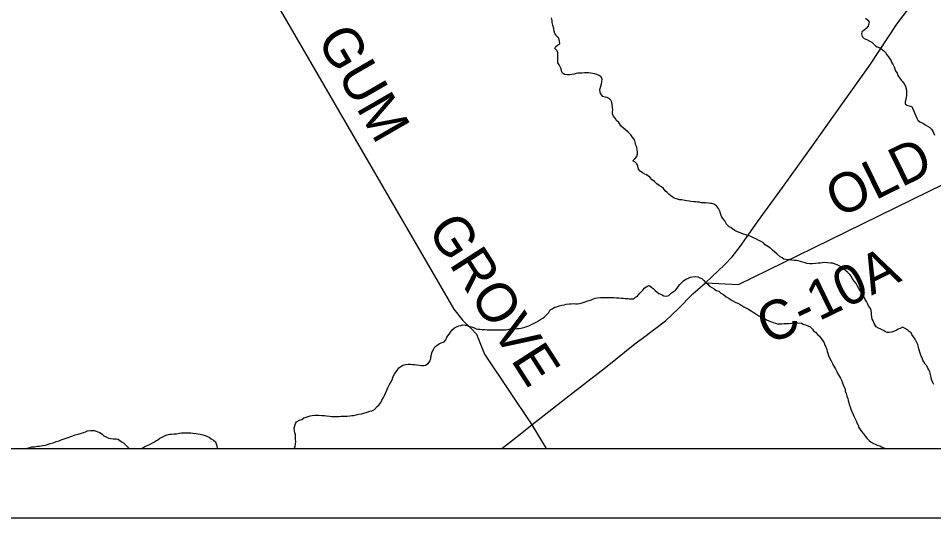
# Model space of a CAD drawing. Extents: x 0.4 to 34.4, y -2.1 to 19.9.
# Drawn here: x 7.097 to 8.419, y 11.936 to 12.657 of the extents above; entities that cross this region are included whole.
import ezdxf

# ---------------------------------------------------------------- set-up
doc = ezdxf.new("R2010")
doc.units = 0
for name, color, linetype in [('GM_X_County', 7, 'Continuous'), ('GM_X_County_Road', 7, 'Continuous'), ('GM_X_County_Road_Text', 7, 'Continuous'), ('GM_X_Minor_River', 7, 'Continuous'), ('GM_X_Township', 7, 'Continuous'), ('GM_X_Township_Road', 7, 'Continuous'), ('GM_X_Township_Road_Text', 7, 'Continuous'), ('GM_X_US_Route', 7, 'Continuous'), ('SH_Data', 7, 'Continuous')]:
    doc.layers.add(name, color=color, linetype=linetype)

msp = doc.modelspace()

# ---------------------------------------------------------------- linework, layer by layer
at = {"layer": 'GM_X_County'}
msp.add_lwpolyline([(9.8001, 15.3423), (9.8001, 18.8357), (3.0001, 18.8357), (3.0001, 12.0357), (9.5074, 12.0357)], dxfattribs=at)
at = {"layer": 'GM_X_County_Road'}
msp.add_lwpolyline([(8.0891, 12.2752), (8.137, 12.2725), (8.245, 12.3255), (8.4821, 12.4414), (8.5989, 12.4995), (8.628, 12.5138), (8.6707, 12.5221), (8.7165, 12.5201), (8.7516, 12.5061), (8.8108, 12.4713), (8.8447, 12.457), (8.8853, 12.4579)], dxfattribs=at)
at = {"layer": 'GM_X_Minor_River'}
for points in [[(8.0158, 12.4213), (8.0121, 12.4236), (8.0087, 12.4275), (8.0042, 12.431), (8.0016, 12.4322), (7.9982, 12.4341), (7.9948, 12.4361), (7.9926, 12.4392), (7.9915, 12.4434), (7.9901, 12.4468), (7.9879, 12.4495), (7.9845, 12.4515), (7.9872, 12.4541), (7.99, 12.4575), (7.9912, 12.4609), (7.9913, 12.4643), (7.9906, 12.467), (7.9899, 12.4708), (7.9888, 12.4739), (7.9881, 12.4765), (7.987, 12.48), (7.9852, 12.4834), (7.9834, 12.4861), (7.9815, 12.4888), (7.9778, 12.4927), (7.9737, 12.4962), (7.9707, 12.4986), (7.9673, 12.5013), (7.964, 12.5067), (7.9606, 12.5094), (7.9588, 12.5128), (7.9562, 12.5156), (7.9551, 12.519), (7.9552, 12.5217), (7.9553, 12.5255), (7.955, 12.5281), (7.9547, 12.5316), (7.954, 12.5358), (7.9525, 12.5388), (7.9503, 12.5415), (7.9473, 12.5427), (7.9446, 12.5432), (7.9412, 12.5444), (7.9375, 12.5486), (7.9368, 12.5532), (7.9373, 12.5558), (7.9381, 12.5593), (7.9389, 12.5623), (7.9394, 12.5653), (7.9402, 12.5691), (7.9388, 12.5726), (7.9358, 12.5745), (7.9324, 12.5761), (7.9294, 12.5769), (7.9267, 12.5773), (7.9237, 12.5778), (7.9202, 12.5782), (7.9172, 12.5783), (7.9145, 12.5783), (7.9107, 12.578), (7.9077, 12.5781), (7.905, 12.5777), (7.9023, 12.5774), (7.8996, 12.5767), (7.8962, 12.576), (7.8935, 12.5757), (7.8893, 12.5757), (7.8859, 12.5762), (7.8829, 12.5781), (7.8814, 12.5808), (7.8807, 12.5843), (7.8793, 12.587), (7.8782, 12.59), (7.876, 12.5927), (7.876, 12.5954), (7.8761, 12.5988), (7.8762, 12.6022), (7.8762, 12.6049), (7.8759, 12.6076), (7.8748, 12.6106), (7.8719, 12.6137), (7.8731, 12.6164), (7.8758, 12.6182), (7.8789, 12.6204), (7.8786, 12.6243), (7.8775, 12.6285), (7.8746, 12.6316), (7.8716, 12.635), (7.8709, 12.6385), (7.8702, 12.6427), (7.8688, 12.6473), (7.8681, 12.6511), (7.8678, 12.6541), (7.8668, 12.658)], [(8.3201, 12.6576), (8.3231, 12.6549), (8.3257, 12.6522), (8.3248, 12.6484), (8.324, 12.6458), (8.3213, 12.6424), (8.3181, 12.6398), (8.315, 12.6376), (8.3146, 12.6349), (8.3153, 12.6307), (8.3183, 12.628), (8.3221, 12.6268), (8.3258, 12.6248), (8.3296, 12.6228), (8.3348, 12.6174), (8.3374, 12.6162), (8.3408, 12.6143), (8.3442, 12.6119), (8.3468, 12.6103), (8.3491, 12.6076), (8.3513, 12.6042), (8.3535, 12.6015), (8.3553, 12.5984), (8.3572, 12.5957), (8.3583, 12.593), (8.3601, 12.5899), (8.3616, 12.5873), (8.3626, 12.5842), (8.3637, 12.5811), (8.3659, 12.5777), (8.367, 12.5746), (8.3692, 12.5711), (8.3718, 12.568), (8.374, 12.5653), (8.3763, 12.5626), (8.3781, 12.5592), (8.3788, 12.5557), (8.3795, 12.5523), (8.3794, 12.5485), (8.3793, 12.5458), (8.3789, 12.5432), (8.3784, 12.5398), (8.3776, 12.5364), (8.3775, 12.5337), (8.3801, 12.5318), (8.3836, 12.5309), (8.387, 12.5297), (8.3888, 12.5263), (8.3902, 12.5232), (8.3917, 12.5197), (8.3928, 12.5163), (8.3942, 12.5129), (8.3957, 12.5098), (8.3987, 12.5074), (8.4013, 12.5066), (8.404, 12.5054), (8.4066, 12.5035), (8.41, 12.5015), (8.413, 12.4992), (8.4156, 12.4972), (8.4174, 12.4942), (8.4185, 12.4915), (8.42, 12.4884)], [(8.3219, 12.2479), (8.3197, 12.251), (8.3182, 12.2544), (8.3171, 12.2571), (8.3149, 12.2602), (8.3127, 12.264), (8.3105, 12.2667), (8.3083, 12.2713), (8.3068, 12.274), (8.3046, 12.2767), (8.3013, 12.2814), (8.3002, 12.284), (8.2976, 12.2871), (8.2946, 12.2898), (8.292, 12.2922), (8.2883, 12.2957), (8.2856, 12.2976), (8.2823, 12.2996), (8.2796, 12.3012), (8.2766, 12.302), (8.2732, 12.3032), (8.2698, 12.3036), (8.2656, 12.3041), (8.2614, 12.3042), (8.2579, 12.3038), (8.2553, 12.3035), (8.2518, 12.3032), (8.248, 12.3029), (8.2431, 12.3026), (8.24, 12.3026), (8.2358, 12.3031), (8.2332, 12.3039), (8.2298, 12.3047), (8.2233, 12.3068), (8.2207, 12.3072), (8.218, 12.3072), (8.2138, 12.3077), (8.2104, 12.3081), (8.2077, 12.3082), (8.2051, 12.3086), (8.2024, 12.3094), (8.1998, 12.311), (8.1971, 12.3126), (8.1927, 12.3164), (8.1889, 12.3199), (8.1859, 12.3223), (8.1829, 12.325), (8.1792, 12.3273), (8.1754, 12.3301), (8.1728, 12.3328), (8.1698, 12.3347), (8.1664, 12.3363), (8.163, 12.3379), (8.1585, 12.3399), (8.1536, 12.3423), (8.1509, 12.3431), (8.1475, 12.3443), (8.1441, 12.3455), (8.1407, 12.3467), (8.1381, 12.3475), (8.1347, 12.3491), (8.1317, 12.3507), (8.1287, 12.3526), (8.126, 12.3549), (8.1234, 12.3561), (8.1197, 12.36), (8.1171, 12.3646), (8.1149, 12.3673), (8.113, 12.37), (8.1116, 12.3739), (8.1102, 12.3784), (8.108, 12.3823), (8.1054, 12.3861), (8.1024, 12.3881), (8.099, 12.3897), (8.0963, 12.3897), (8.0937, 12.3902), (8.0895, 12.3906), (8.0857, 12.3907), (8.083, 12.3907), (8.0804, 12.3915), (8.0777, 12.3916), (8.075, 12.392), (8.0724, 12.3921), (8.0686, 12.3925), (8.0655, 12.393), (8.0625, 12.3934), (8.0594, 12.3938), (8.0553, 12.3947), (8.0515, 12.3951), (8.0473, 12.3963), (8.0439, 12.3975), (8.0413, 12.3991), (8.0364, 12.403), (8.0338, 12.4053), (8.0312, 12.408), (8.0286, 12.4111), (8.0259, 12.4135), (8.0222, 12.4158), (8.0188, 12.4178), (8.0158, 12.4213)], [(7.8952, 12.2447), (7.899, 12.245), (7.9017, 12.2449), (7.9043, 12.2449), (7.9078, 12.2452), (7.9112, 12.2459), (7.9155, 12.2477), (7.9193, 12.2492), (7.9231, 12.2502), (7.9274, 12.2517), (7.9301, 12.2528), (7.9327, 12.2531), (7.9377, 12.2538), (7.9404, 12.2537), (7.9438, 12.2537), (7.9472, 12.2536), (7.9503, 12.2539), (7.9537, 12.2539), (7.9568, 12.2538), (7.9606, 12.2534), (7.9644, 12.2533), (7.9678, 12.2528), (7.9705, 12.2528), (7.9735, 12.2524), (7.9769, 12.2523), (7.9796, 12.2519), (7.9823, 12.2518), (7.9857, 12.2521), (7.9884, 12.2544), (7.9911, 12.2558), (7.9935, 12.2592), (7.9966, 12.2618), (7.9989, 12.2645), (8.0017, 12.2678), (8.0052, 12.27), (8.0079, 12.2711), (8.0112, 12.2688), (8.0139, 12.2668), (8.0165, 12.2641), (8.0195, 12.2614), (8.0221, 12.2598), (8.0266, 12.2575), (8.0293, 12.2563), (8.0327, 12.2558), (8.0361, 12.2565), (8.0396, 12.2599), (8.0431, 12.2625), (8.0458, 12.2644), (8.0482, 12.2674), (8.0502, 12.27), (8.0521, 12.2726), (8.0545, 12.2752), (8.0576, 12.2778), (8.0611, 12.2801), (8.0645, 12.2819), (8.0676, 12.283), (8.0703, 12.2837), (8.0749, 12.284), (8.0783, 12.2839), (8.0809, 12.2824), (8.084, 12.2812), (8.087, 12.2784), (8.0892, 12.2757), (8.0922, 12.2734), (8.0952, 12.2703), (8.0985, 12.2683), (8.1016, 12.2664), (8.1049, 12.264), (8.1083, 12.2628), (8.1113, 12.2601), (8.1151, 12.2581), (8.1192, 12.255), (8.1222, 12.2531), (8.1249, 12.2515), (8.1279, 12.2495), (8.1331, 12.2468), (8.1358, 12.2456), (8.1392, 12.2436), (8.1418, 12.2421), (8.1448, 12.2405), (8.1474, 12.2389), (8.1512, 12.2369), (8.155, 12.2346), (8.158, 12.2326), (8.1606, 12.2311), (8.1632, 12.2291), (8.1662, 12.2275), (8.17, 12.2256), (8.1738, 12.224), (8.1776, 12.2216), (8.1809, 12.22), (8.1844, 12.2188), (8.187, 12.2176), (8.1904, 12.2168), (8.1934, 12.216), (8.1969, 12.2159), (8.1995, 12.2159), (8.203, 12.2162), (8.2064, 12.2161), (8.2102, 12.2164), (8.2137, 12.2168)], [(7.6007, 12.088), (7.6046, 12.0895), (7.6073, 12.0902), (7.6111, 12.092), (7.615, 12.0961), (7.6177, 12.0983), (7.6205, 12.1021), (7.6221, 12.1055), (7.6241, 12.1093), (7.6257, 12.1123), (7.6277, 12.1164), (7.6289, 12.1198), (7.6305, 12.1232), (7.6329, 12.1281), (7.6349, 12.1315), (7.6369, 12.1349), (7.6385, 12.1398), (7.6409, 12.144), (7.644, 12.1485), (7.6464, 12.1522), (7.6495, 12.1541), (7.6522, 12.1559), (7.6561, 12.157), (7.6599, 12.1573), (7.6633, 12.1576), (7.6664, 12.1572), (7.669, 12.1571), (7.6724, 12.1563), (7.6759, 12.1559), (7.6793, 12.1554), (7.6823, 12.1554), (7.685, 12.1561), (7.6889, 12.1583), (7.6912, 12.1617), (7.6925, 12.1655), (7.6933, 12.17), (7.6946, 12.1753), (7.6966, 12.1787), (7.6982, 12.1825), (7.7013, 12.1847), (7.7052, 12.1873), (7.709, 12.1887), (7.7117, 12.1898), (7.7141, 12.1928), (7.716, 12.1966), (7.7192, 12.2007), (7.7212, 12.2037), (7.7235, 12.2071), (7.727, 12.2101), (7.7305, 12.2119), (7.7332, 12.213), (7.7359, 12.2134), (7.7389, 12.2141), (7.742, 12.214), (7.745, 12.2136), (7.7477, 12.2124), (7.7514, 12.2112), (7.7541, 12.2104), (7.7579, 12.2084), (7.7605, 12.2083), (7.7632, 12.2079), (7.7666, 12.2078), (7.7704, 12.2078), (7.7739, 12.2073), (7.7773, 12.2073), (7.78, 12.2072), (7.783, 12.2072), (7.7868, 12.2071), (7.7902, 12.207), (7.7937, 12.207), (7.7967, 12.2069), (7.8005, 12.2072), (7.8032, 12.2076), (7.8059, 12.2079), (7.8101, 12.2082), (7.8135, 12.2085), (7.817, 12.2088), (7.8204, 12.2091), (7.825, 12.2102), (7.8285, 12.2109), (7.8312, 12.212), (7.8342, 12.2131), (7.8388, 12.2153), (7.8419, 12.2167), (7.8458, 12.2186), (7.8485, 12.2204), (7.8516, 12.2223), (7.8543, 12.2241), (7.857, 12.226), (7.8597, 12.229), (7.8629, 12.2323), (7.8652, 12.2361), (7.8679, 12.2376), (7.8718, 12.2398), (7.8745, 12.2405), (7.878, 12.2419), (7.8818, 12.2426), (7.8856, 12.2433), (7.8883, 12.244), (7.8925, 12.2447), (7.8952, 12.2447)], [(8.4191, 12.1282), (8.4173, 12.132), (8.4154, 12.1355), (8.4151, 12.1389), (8.4144, 12.1427), (8.4134, 12.1462), (8.4119, 12.1492), (8.4105, 12.1519), (8.409, 12.155), (8.4064, 12.1577), (8.4046, 12.1608), (8.4031, 12.1635), (8.402, 12.1665), (8.4006, 12.1692), (8.3995, 12.1719), (8.3984, 12.1761), (8.3974, 12.1795), (8.3967, 12.1822), (8.396, 12.186), (8.3934, 12.1906), (8.392, 12.1937), (8.3894, 12.1972), (8.3871, 12.2003), (8.3861, 12.203), (8.3834, 12.2049), (8.3808, 12.2072), (8.3767, 12.2096), (8.3737, 12.2108), (8.3706, 12.2089), (8.3675, 12.2079), (8.3648, 12.206), (8.3609, 12.2046), (8.3579, 12.2035), (8.3544, 12.2032), (8.3518, 12.2032), (8.3491, 12.204), (8.3461, 12.2063), (8.3423, 12.2079), (8.3393, 12.2095), (8.3359, 12.2115), (8.333, 12.2161), (8.3312, 12.2199), (8.3301, 12.2226), (8.3294, 12.2257), (8.3291, 12.2291), (8.3288, 12.2318), (8.3285, 12.2348), (8.3274, 12.2379), (8.3248, 12.2417), (8.3237, 12.2444), (8.3219, 12.2479)], [(8.2137, 12.2168), (8.2163, 12.2171), (8.2198, 12.217), (8.2228, 12.217), (8.2278, 12.2165), (8.2304, 12.2153), (8.2338, 12.2145), (8.2372, 12.2129), (8.2406, 12.2113), (8.2436, 12.2082), (8.2454, 12.2055), (8.2481, 12.2036), (8.2514, 12.2001), (8.254, 12.1978), (8.2562, 12.1947), (8.2588, 12.1912), (8.2607, 12.1885), (8.2618, 12.1851), (8.2628, 12.1824), (8.2643, 12.1786), (8.265, 12.1759), (8.2661, 12.1732), (8.2671, 12.1701), (8.2689, 12.1655), (8.2708, 12.1621), (8.2726, 12.1586), (8.2737, 12.1559), (8.277, 12.1506), (8.2788, 12.1471), (8.2803, 12.1436), (8.2828, 12.1398), (8.2843, 12.1371), (8.2858, 12.1344), (8.2872, 12.1306), (8.2879, 12.1275), (8.2894, 12.1245), (8.2908, 12.1214), (8.2911, 12.1183), (8.2926, 12.1149), (8.2936, 12.1111), (8.2947, 12.108), (8.2954, 12.1049), (8.2961, 12.1023), (8.2968, 12.0996), (8.2982, 12.0958), (8.2989, 12.0927), (8.3008, 12.0889), (8.3026, 12.0846), (8.304, 12.0812), (8.3055, 12.0785), (8.3066, 12.0758), (8.308, 12.0728), (8.3095, 12.0693), (8.3109, 12.0662), (8.3128, 12.0632), (8.315, 12.0597), (8.3176, 12.0566), (8.3202, 12.0531), (8.322, 12.0504), (8.3254, 12.0473), (8.3287, 12.0446), (8.3317, 12.043), (8.3344, 12.0418), (8.337, 12.0406), (8.3408, 12.0394), (8.3435, 12.0382), (8.3476, 12.0363), (8.3497, 12.0357)], [(7.4957, 12.0357), (7.4959, 12.0359), (7.4967, 12.0389), (7.4971, 12.042), (7.4976, 12.0458), (7.4973, 12.0488), (7.4974, 12.0515), (7.4971, 12.0553), (7.4964, 12.0583), (7.4957, 12.061), (7.4954, 12.0648), (7.4962, 12.0686), (7.4974, 12.0716), (7.4986, 12.0743), (7.5029, 12.0765), (7.5063, 12.0776), (7.5094, 12.0798), (7.5125, 12.0809), (7.5156, 12.082), (7.5186, 12.0827), (7.5213, 12.0834), (7.5251, 12.0837), (7.5278, 12.0836), (7.5309, 12.0836), (7.5351, 12.0835), (7.5389, 12.0834), (7.5419, 12.083), (7.5461, 12.0825), (7.5487, 12.0817), (7.5514, 12.0817), (7.5552, 12.082), (7.5602, 12.0819), (7.5632, 12.0822), (7.5659, 12.0822), (7.5693, 12.0825), (7.572, 12.0824), (7.5755, 12.0828), (7.5785, 12.0831), (7.5812, 12.0834), (7.585, 12.0841), (7.5885, 12.0852), (7.5927, 12.0859), (7.5961, 12.0866), (7.6007, 12.088)], [(7.1076, 12.0357), (7.1096, 12.0361), (7.1135, 12.0372), (7.1162, 12.0379), (7.1204, 12.0382), (7.1249, 12.0389), (7.1276, 12.0392), (7.1322, 12.0399), (7.1364, 12.0406), (7.143, 12.0428), (7.1472, 12.0438), (7.1518, 12.0456), (7.156, 12.0467), (7.1591, 12.0482), (7.1618, 12.0493), (7.1691, 12.0514), (7.1729, 12.0529), (7.1756, 12.054), (7.1791, 12.0554), (7.1833, 12.0565), (7.1883, 12.0579), (7.1914, 12.059), (7.194, 12.0597), (7.1971, 12.0612), (7.201, 12.0615), (7.2036, 12.0618), (7.2063, 12.0618), (7.2093, 12.0609), (7.212, 12.0598), (7.2146, 12.0589), (7.218, 12.0562), (7.2206, 12.0539), (7.224, 12.0523), (7.2274, 12.0507), (7.2304, 12.0503), (7.2339, 12.0498), (7.2381, 12.0498), (7.2407, 12.049), (7.2433, 12.0478), (7.246, 12.0454), (7.249, 12.0439), (7.2516, 12.0411), (7.2542, 12.0384), (7.2568, 12.0361), (7.258, 12.0357)], [(7.2746, 12.0357), (7.2766, 12.0365), (7.2797, 12.0383), (7.2844, 12.0405), (7.2882, 12.0424), (7.2925, 12.045), (7.2956, 12.0468), (7.2983, 12.0483), (7.3014, 12.0505), (7.3056, 12.0527), (7.3091, 12.0542), (7.3121, 12.0553), (7.3156, 12.0563), (7.3183, 12.0563), (7.3221, 12.0566), (7.3255, 12.0569), (7.3297, 12.0576), (7.3324, 12.0583), (7.3358, 12.0582), (7.3393, 12.0582), (7.3423, 12.0581), (7.3461, 12.0581), (7.3488, 12.058), (7.3538, 12.0575), (7.3568, 12.0567)], [(7.3568, 12.0567), (7.3598, 12.0563), (7.3632, 12.0555), (7.367, 12.0542), (7.37, 12.053), (7.3727, 12.0519), (7.3757, 12.0495), (7.3787, 12.0476), (7.3817, 12.0452), (7.3828, 12.0422), (7.3838, 12.0395), (7.3842, 12.0368), (7.3838, 12.0357)]]:
    msp.add_lwpolyline(points, dxfattribs=at)
at = {"layer": 'GM_X_Township'}
msp.add_line((4.0866, 12.0357), (9.5074, 12.0357), dxfattribs=at)
at = {"layer": 'GM_X_Township_Road'}
for points in [[(7.3419, 12.8996), (7.7257, 12.237), (7.7391, 12.2208), (7.751, 12.2088), (7.7586, 12.2008), (7.7702, 12.1721), (7.8386, 12.0698)], [(7.8386, 12.0698), (7.8594, 12.0357)]]:
    msp.add_lwpolyline(points, dxfattribs=at)
at = {"layer": 'GM_X_US_Route'}
for points in [[(7.9931, 12.1913), (7.9976, 12.1948), (8.0316, 12.2202), (8.0496, 12.2375), (8.071, 12.2589), (8.0891, 12.2752), (8.1165, 12.3008), (8.1279, 12.3125), (8.1391, 12.3275), (8.1644, 12.3629), (8.2005, 12.4129), (8.2447, 12.4746), (8.2869, 12.534), (8.3265, 12.5897), (8.3657, 12.6487), (8.4022, 12.6972), (8.4429, 12.7559)], [(7.8151, 12.0513), (7.8386, 12.0698), (7.8877, 12.1084), (7.945, 12.1529), (7.9874, 12.1867), (7.9931, 12.1913)], [(7.7952, 12.0357), (7.8064, 12.0444), (7.8151, 12.0513)]]:
    msp.add_lwpolyline(points, dxfattribs=at)
at = {"layer": 'SH_Data'}
for p, q in [((3.0001, 12.0357), (9.8001, 12.0357)), ((2.9001, 11.9357), (9.9001, 11.9357))]:
    msp.add_line(p, q, dxfattribs=at)

# ---------------------------------------------------------------- texts
at = {"layer": 'GM_X_County_Road_Text'}
for s, rotation, p in [('OLD', 26.1142, (8.2812, 12.368)), ('C-10A', 25.9981, (8.181, 12.1842))]:
    msp.add_text(s, height=0.05682, rotation=rotation, dxfattribs=at).set_placement(p)
at = {"layer": 'GM_X_Township_Road_Text'}
for s, rotation, p in [('GUM', 300.0015, (7.5271, 12.6267)), ('GROVE', 302.7025, (7.6864, 12.352))]:
    msp.add_text(s, height=0.05682, rotation=rotation, dxfattribs=at).set_placement(p)

doc.saveas('drawing.dxf')
